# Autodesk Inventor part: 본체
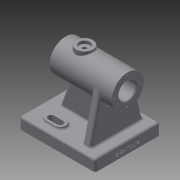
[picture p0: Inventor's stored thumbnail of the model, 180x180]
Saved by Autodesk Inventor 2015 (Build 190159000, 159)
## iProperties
Created: 2022-06
Part Number: 본체
Material: 일반
Document SubType Name: Modeling
Designer: 104-1
Density: 1 g/cm^3
Appearance: 기본값
Author: 104-1
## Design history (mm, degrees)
sketch "스케치1"
  geometry: L1 (-50, -43)-(50, -43); L2 (50, -43)-(50, 43); L3 (50, 43)-(-50, 43); L4 (-50, 43)-(-50, -43); L5 (-50, -43)-(50, 43); L6 (50, -43)-(-50, 43); 1 further point
  constraints: 12 end point, 2 midpoint, 2 parallel, 1 horizontal, 1 perpendicular
  dimensions: "d0" = 100 distance of L2.end L3.end; "d1" = 86 distance of L1.end L2.end
extrude "돌출1" new body sketch "스케치1" distance "d2" = 15; taper "d3" = 0 deg
sketch "스케치3"
  geometry: L1 (50, -43)-(50, 43) reference; L2 (50, 43)-(-50, 43) reference; L3 (-50, 43)-(-50, -43) reference; L4 (25, 35)-(35, 35); L5 (35, 35)-(35, -35); L6 (35, -35)-(25, -35); L7 (25, -35)-(25, 35); L8 (-35, 5)-(35, 5); L9 (35, 5)-(35, -5); L10 (35, -5)-(-35, -5); L11 (-35, -5)-(-35, 5); L12 (-50, 0)-(50, 0); 1 further point
  constraints: 18 end point, 4 parallel, 2 horizontal, 2 midpoint, 2 perpendicular, 2 other
  dimensions: "d4" = 15 distance between parallel lines of L1 L5; "d5" = 15 distance between parallel lines of L1 L9; "d6" = 10 distance of L4.start L4.end; "d7" = 10 distance of L10.end L8.start; "d8" = 15 distance between parallel lines of L3 L11; "d9" = 8 distance between parallel lines of L2 L4
extrude "돌출2" join sketch "스케치3" distance "d10" = 57; taper "d11" = 0 deg
sketch "스케치4"
  geometry: L1 (50, 43)-(-50, 43) reference; L2 (-50, 43)-(-50, -43) reference; L3 (-31, 20)-(-5, 20); L4 (-5, 20)-(-5, 34); L5 (-5, 34)-(-31, 34); L6 (-31, 34)-(-31, 20); L7 (-31, 20)-(-5, 34); L8 (-5, 20)-(-31, 34); L9 (-24, 34)-(-12, 34); L10 (-24, 20)-(-12, 20); A1 r 7 centre (-24, 27) between (-24, 34) and (-24, 20); A2 r 7 centre (-12, 27) between (-18.98, 27.528) and (-18.98, 26.472); A3 r 7 centre (-12, 27) between (-12, 20) and (-12, 34); 4 further points
  constraints: 16 end point, 6 point on circle, 6 point on line, 3 centre point, 2 coincident, 2 horizontal alignment, 2 midpoint, 2 parallel, 1 horizontal, 1 perpendicular, 1 tangent
  dimensions: "d12" = 26 distance from line of point (-24, 27) L2; "d13" = 16 distance from line of L1 point (-24, 27); "d14" = 12 distance of point (-12, 27) point (-24, 27); "d15" = 6 distance of point (-18, 27) point (-24, 27); "d16" = 26 distance of L4.end L5.end; "d17" = 14 distance of L3.end L4.end
extrude "돌출3" join sketch "스케치4" distance "d19" = 3; taper "d20" = 0 deg
sketch "스케치5"
  geometry: L1 (-12, 34)-(-24, 34) reference; L2 (-24, 20)-(-12, 20) reference; L3 (-24, 31)-(-12, 31); L4 (-12, 23)-(-24, 23); A1 r 7 centre (-12, 27) between (-12, 20) and (-12, 34) reference; A2 r 7 centre (-24, 27) between (-24, 34) and (-24, 20) reference; A3 r 4 centre (-24, 27) between (-24, 31) and (-24, 23); A4 r 4 centre (-12, 27) between (-12, 23) and (-12, 31); 1 further point
  constraints: 4 end point, 4 point on circle, 2 centre point, 3 other
  dimensions: "d21" = 3 radial gap between concentric circles of A2 A3
extrude "돌출4" cut sketch "스케치5" stored distance "d22" = 3; taper "d23" = 0 deg
sketch "스케치7"
  geometry: L1 (0, 10)-(0, 0) reference; L2 (0, 10)-(-57, 10) reference; L3 (-57, 0)-(-57, 10) reference; L4 (0, 0)-(-57, 0) reference; L5 (15, -38)-(0, -38) reference; L6 (0, 48)-(0, -38) reference; L7 (0, -30)-(-61.814, -15.441); L8 (0, 40)-(-61.814, 25.441); L9 (-61.814, -15.441)-(-61.814, 25.441); L10 (0, -30)-(0, 40); A1 r 21 centre (-57, 5) between (-61.814, -15.441) and (-61.814, 25.441); 1 further point
  constraints: 8 end point, 2 point on circle, 2 tangent, 1 centre point, 1 midpoint, 1 point on line, 1 vertical, 1 vertical alignment
  dimensions: "d25" = 42 diameter of A1; "d26" = 8 distance from line of L7.start L5; "d27" = 8 distance of L6.start L8.start
extrude "돌출5" join sketch "스케치7" distance "d28" = 10; taper "d29" = 0 deg
feature "면 기울기1" dims angle "d30" = 20 deg
fillet "모깎기1" dims "d31" = 3
sketch "스케치8"
  geometry: L1 (32, 93)-(-50, 93); L2 (-50, 93)-(-50, 72); L3 (-50, 72)-(32, 72); L4 (32, 72)-(32, 93); L5 (-50, 0)-(-50, 15) reference; L6 (-50, 15)-(-35, 15) reference; L7 (-35, 15)-(-35, 76.814) reference; L8 (-35, 76.814)-(-25, 76.814) reference; L9 (-25, 76.814)-(-25, 72) reference; L10 (-25, 72)-(14.254, 72) reference; L11 (14.254, 72)-(35, 15) reference; L12 (35, 15)-(50, 15) reference; L13 (50, 15)-(50, 0) reference; L14 (50, 0)-(-50, 0) reference; L15 (-50, 0)-(-50, 15) reference; 2 further points
  constraints: 8 end point, 2 parallel, 1 horizontal, 1 midpoint, 1 perpendicular, 1 point on line
  dimensions: "d32" = 21 distance of L1.end L2.end; "d33" = 82 distance of L1.start L1.end; "d34" = 0 distance between parallel lines of L5 L2
revolve "회전1" sketch "스케치8" stored, may be unused: angle "d35" = 90 deg
fillet "모깎기2" dims "d36" = 3
fillet "모깎기3" dims "d37" = 3
sketch "스케치9"
  geometry: C1 r 21 at (0, 0) reference; 1 further point
hole "구멍1" sketch "스케치9" at (0, 0) diameter "d38" = 23; stored, may be unused: countersink angle "d42" = 90 deg, drill point angle "d44" = 0 deg; dims "d39" = 6, "d40" = 29, "d41" = 62, "d43" = 82
node "작업 평면1"
sketch "스케치10"
  geometry: L1 (-32, 21)-(-32, -21) reference; C1 r 11 at (-7, 0); 1 further point
  constraints: 1 centre point
  dimensions: "d46" = 25 distance from line of C1.centre L1; "d47" = 22 diameter of C1
extrude "돌출6" join sketch "스케치10" stored distance "d48" = 82; taper "d49" = 0 deg
sketch "스케치11"
  geometry: C1 r 11 at (0, 0) reference; 1 further point
hole "구멍2" sketch "스케치11" at (0, 0) diameter "d50" = 14; stored, may be unused: countersink angle "d54" = 90 deg, drill point angle "d56" = 0 deg; dims "d51" = 6, "d52" = 29, "d53" = 62, "d55" = 4
sketch "스케치12"
  geometry: 2 further points
  constraints: 1 horizontal alignment
hole "구멍3" sketch "스케치12" at (0, 0) diameter "d57" = 4.917; stored, may be unused: countersink angle "d61" = 90 deg, drill point angle "d63" = 0 deg; dims "d58" = 10, "d59" = 29, "d60" = 62, "d62" = 10
sketch "스케치13"
  geometry: C1 r 14.5 at (0, 0) reference; 2 further points
  dimensions: "d64" = 18 distance of C1.centre point (18, 0)
hole "구멍4" sketch "스케치13" at (18, 0) diameter "d65" = 2.459; stored, may be unused: countersink angle "d69" = 90 deg, drill point angle "d71" = 118 deg; dims "d66" = 8, "d67" = 29, "d68" = 62, "d70" = 10
sketch "스케치14"
  geometry: C1 r 11.5 at (0, 0) reference; 2 further points
  constraints: 1 horizontal alignment
  dimensions: "d75" = 18 distance of C1.centre point (-18, 0)
hole "구멍5" sketch "스케치14" at (-18, 0) diameter "d76" = 2.459; stored, may be unused: countersink angle "d80" = 90 deg, drill point angle "d82" = 118 deg; dims "d77" = 8, "d78" = 29, "d79" = 62, "d81" = 10
fillet "모깎기4" dims "d86" = 1
fillet "모깎기5" dims "d87" = 3
fillet "모깎기6" dims "d88" = 3
sketch "스케치15"
  geometry: L1 (0, 0)-(0, 80) reference; 3 further points
  constraints: 1 horizontal alignment, 1 midpoint, 1 other
  dimensions: "d89" = 6 distance of point (0, 40) point (-6, 40)
feature "엠보싱1" sketch "스케치15" dims "d0" = 100, "d1" = 86, "d4" = 15, "d5" = 15, "d6" = 10, "d7" = 10, "d8" = 15, "d9" = 8, "d90" = 0.5, "d91" = 0
fillet "모깎기7" dims "d92" = 3
fillet "모깎기8" dims "d93" = 3
chamfer "모따기1" distance "d94" = 1; stored, may be unused: second distance "d95" = 2, angle "d96" = 45 deg
node "솔리드1"
mirror "대칭1"
pattern_circular "원형 패턴1" dims angle "d73" = 360 deg
pattern_circular "원형 패턴2" dims angle "d84" = 360 deg
node "절단 모서리 투영1"
other parameters: "d18" = 14, "d45" = 96
